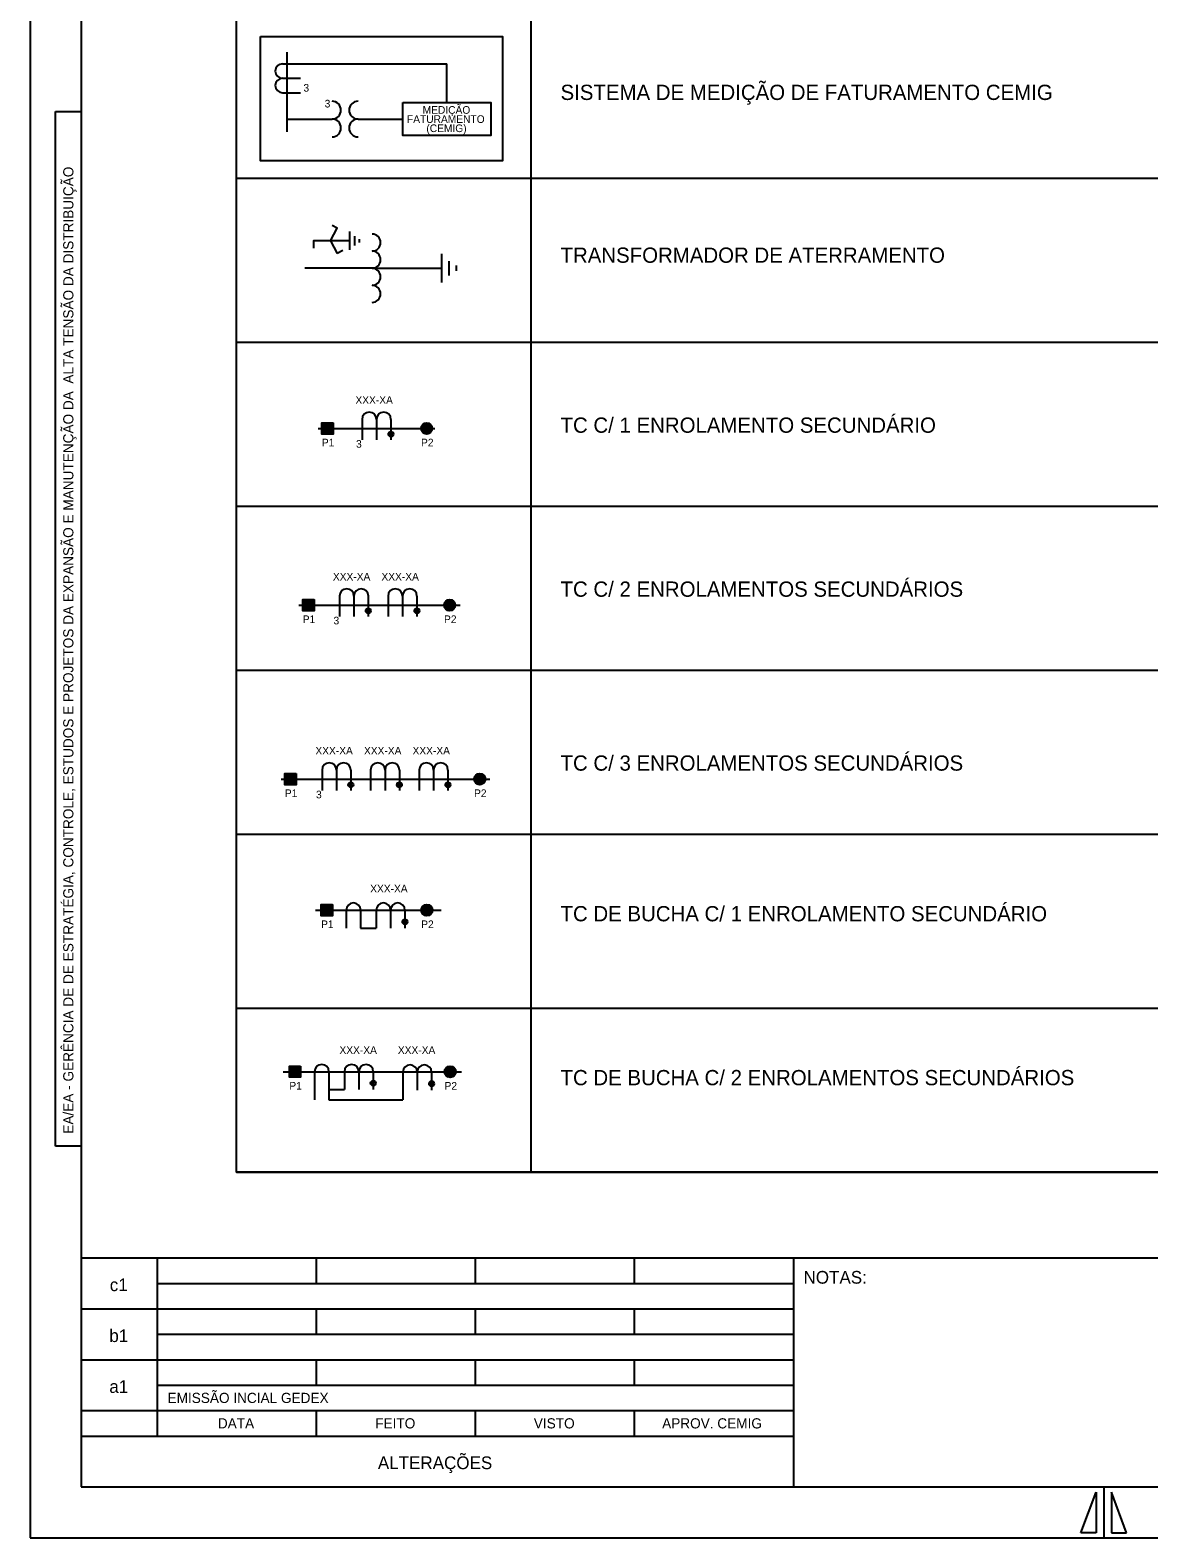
# Model space of a CAD drawing. Extents: x 563 to 3226, y 358 to 960.
# Drawn here: x 562.6 to 782.4, y 358 to 654.3 of the extents above; entities that cross this region are included whole.
import ezdxf

# ---------------------------------------------------------------- set-up
doc = ezdxf.new("R2010")
doc.units = 0
for name, color, linetype in [('11', 7, 'Continuous'), ('COMENTÁRIOS_CEMIG_03-12-2019', 7, 'Continuous'), ('Default', 7, 'Continuous'), ('Level 2', 7, 'Continuous'), ('New Level (0)', 7, 'Continuous')]:
    doc.layers.add(name, color=color, linetype=linetype)

msp = doc.modelspace()

# ---------------------------------------------------------------- linework, layer by layer
for p, q in [((627.23, 613.23), (627.23, 612.54)), ((646.28, 608.02), (646.28, 606.95))]:
    msp.add_line(p, q)
at = {"layer": '11'}
for p, q in [((621.62, 612.88), (622.94, 610.38)), ((624.02, 610.95), (622.94, 610.38)), ((629.78, 607.49), (616.59, 607.49)), ((630.42, 607.49), (629.78, 607.49))]:
    msp.add_line(p, q, dxfattribs=at)
for points in [[(621.62, 612.88), (622.91, 615.34), (621.94, 615.86)], [(625.43, 612.88), (618.29, 612.88), (618.29, 611.46)]]:
    msp.add_lwpolyline(points, dxfattribs=at)
at = {"layer": 'COMENTÁRIOS_CEMIG_03-12-2019'}
for p, q in [((619.91, 576.99), (622.01, 574.89)), ((619.91, 576.81), (621.83, 574.89)), ((619.91, 576.63), (621.65, 574.89)), ((619.91, 576.45), (621.48, 574.89)), ((619.91, 576.28), (621.3, 574.89)), ((619.91, 576.1), (621.12, 574.89)), ((619.91, 575.92), (620.95, 574.89)), ((619.91, 575.75), (620.77, 574.89)), ((619.91, 575.57), (620.59, 574.89)), ((619.91, 575.39), (620.42, 574.89)), ((619.91, 575.22), (620.24, 574.89)), ((619.91, 575.04), (620.06, 574.89)), ((619.97, 577.1), (622.13, 574.95)), ((620.15, 577.1), (622.13, 575.13)), ((620.33, 577.1), (622.13, 575.3)), ((620.5, 577.1), (622.13, 575.48)), ((620.68, 577.1), (622.13, 575.66)), ((620.86, 577.1), (622.13, 575.83)), ((621.03, 577.1), (622.13, 576.01)), ((621.21, 577.1), (622.13, 576.19)), ((621.39, 577.1), (622.13, 576.36)), ((621.56, 577.1), (622.13, 576.54)), ((621.74, 577.1), (622.13, 576.72)), ((621.92, 577.1), (622.13, 576.9)), ((622.09, 577.1), (622.13, 577.07)), ((616.21, 542.38), (618.37, 540.22)), ((616.39, 542.38), (618.37, 540.4)), ((616.57, 542.38), (618.37, 540.58)), ((616.74, 542.38), (618.37, 540.75)), ((616.92, 542.38), (618.37, 540.93)), ((617.1, 542.38), (618.37, 541.11)), ((617.27, 542.38), (618.37, 541.28)), ((617.45, 542.38), (618.37, 541.46)), ((617.63, 542.38), (618.37, 541.64)), ((617.8, 542.38), (618.37, 541.81)), ((617.98, 542.38), (618.37, 541.99)), ((618.16, 542.38), (618.37, 542.17)), ((618.33, 542.38), (618.37, 542.34)), ((616.16, 542.26), (618.25, 540.17)), ((616.16, 542.08), (618.07, 540.17)), ((616.16, 541.9), (617.89, 540.17)), ((616.16, 541.73), (617.72, 540.17)), ((616.16, 541.55), (617.54, 540.17)), ((616.16, 541.37), (617.36, 540.17)), ((616.16, 541.2), (617.19, 540.17)), ((616.16, 541.02), (617.01, 540.17)), ((616.16, 540.84), (616.83, 540.17)), ((616.16, 540.67), (616.66, 540.17)), ((616.16, 540.49), (616.48, 540.17)), ((616.16, 540.31), (616.3, 540.17)), ((612.64, 508.07), (614.73, 505.98)), ((612.64, 507.89), (614.55, 505.98)), ((612.64, 507.72), (614.38, 505.98)), ((612.64, 507.54), (614.2, 505.98)), ((612.64, 507.36), (614.02, 505.98)), ((612.64, 507.19), (613.85, 505.98)), ((612.64, 507.01), (613.67, 505.98)), ((612.64, 506.83), (613.49, 505.98)), ((612.7, 508.19), (614.85, 506.04)), ((612.87, 508.19), (614.85, 506.21)), ((613.05, 508.19), (614.85, 506.39)), ((613.23, 508.19), (614.85, 506.57)), ((613.4, 508.19), (614.85, 506.74)), ((613.58, 508.19), (614.85, 506.92)), ((613.76, 508.19), (614.85, 507.1)), ((613.93, 508.19), (614.85, 507.27)), ((614.11, 508.19), (614.85, 507.45)), ((614.29, 508.19), (614.85, 507.63)), ((614.46, 508.19), (614.85, 507.8)), ((614.64, 508.19), (614.85, 507.98)), ((614.82, 508.19), (614.85, 508.16)), ((612.64, 506.66), (613.32, 505.98)), ((612.64, 506.48), (613.14, 505.98)), ((612.64, 506.3), (612.96, 505.98)), ((612.64, 506.13), (612.79, 505.98)), ((619.76, 482.31), (621.85, 480.22)), ((619.76, 482.13), (621.67, 480.22)), ((619.76, 481.96), (621.5, 480.22)), ((619.76, 481.78), (621.32, 480.22)), ((619.76, 481.6), (621.14, 480.22)), ((619.76, 481.43), (620.97, 480.22)), ((619.76, 481.25), (620.79, 480.22)), ((619.76, 481.07), (620.61, 480.22)), ((619.76, 480.9), (620.44, 480.22)), ((619.76, 480.72), (620.26, 480.22)), ((619.76, 480.54), (620.08, 480.22)), ((619.76, 480.37), (619.91, 480.22)), ((619.82, 482.43), (621.97, 480.28)), ((619.99, 482.43), (621.97, 480.45)), ((620.17, 482.43), (621.97, 480.63)), ((620.35, 482.43), (621.97, 480.81)), ((620.52, 482.43), (621.97, 480.98)), ((620.7, 482.43), (621.97, 481.16)), ((620.88, 482.43), (621.97, 481.34)), ((621.05, 482.43), (621.97, 481.51)), ((621.23, 482.43), (621.97, 481.69)), ((621.41, 482.43), (621.97, 481.87)), ((621.58, 482.43), (621.97, 482.04)), ((621.76, 482.43), (621.97, 482.22)), ((621.94, 482.43), (621.97, 482.4)), ((613.52, 450.57), (615.61, 448.48)), ((613.58, 450.69), (615.73, 448.54)), ((613.75, 450.69), (615.73, 448.71)), ((613.93, 450.69), (615.73, 448.89)), ((614.11, 450.69), (615.73, 449.07)), ((614.28, 450.69), (615.73, 449.24)), ((614.46, 450.69), (615.73, 449.42)), ((614.64, 450.69), (615.73, 449.6)), ((614.81, 450.69), (615.73, 449.77)), ((614.99, 450.69), (615.73, 449.95)), ((615.17, 450.69), (615.73, 450.13)), ((615.34, 450.69), (615.73, 450.3)), ((615.52, 450.69), (615.73, 450.48)), ((615.7, 450.69), (615.73, 450.66)), ((613.52, 450.39), (615.43, 448.48)), ((613.52, 450.22), (615.26, 448.48)), ((613.52, 450.04), (615.08, 448.48)), ((613.52, 449.86), (614.9, 448.48)), ((613.52, 449.69), (614.73, 448.48)), ((613.52, 449.51), (614.55, 448.48)), ((613.52, 449.33), (614.37, 448.48)), ((613.52, 449.16), (614.2, 448.48)), ((613.52, 448.98), (614.02, 448.48)), ((613.52, 448.8), (613.84, 448.48)), ((613.52, 448.63), (613.67, 448.48))]:
    msp.add_line(p, q, dxfattribs=at)
for points in [[(622.13, 577.1), (622.13, 574.89), (619.91, 574.89), (619.91, 577.1)], [(618.37, 542.38), (618.37, 540.17), (616.16, 540.17), (616.16, 542.38)], [(614.85, 508.19), (614.85, 505.98), (612.64, 505.98), (612.64, 508.19)], [(621.97, 482.43), (621.97, 480.22), (619.76, 480.22), (619.76, 482.43)], [(615.73, 450.69), (615.73, 448.48), (613.52, 448.48), (613.52, 450.69)]]:
    msp.add_lwpolyline(points, close=True, dxfattribs=at)
at = {"layer": 'Default'}
for p, q in [((613.08, 634.27), (613.08, 649.98)), ((612.17, 647.65), (615.7, 647.65)), ((615.7, 647.65), (644.48, 647.65)), ((612.17, 644.82), (615.7, 644.82)), ((612.17, 641.99), (615.7, 641.99)), ((613.08, 636.81), (621.92, 636.81)), ((627.02, 636.81), (635.81, 636.81)), ((627.81, 577.78), (627.81, 573.77)), ((630.65, 577.78), (630.65, 573.77)), ((633.48, 577.78), (633.48, 573.77)), ((639.41, 576.08), (640.59, 574.9)), ((639.41, 575.88), (640.39, 574.9)), ((639.43, 576.25), (640.76, 574.92)), ((639.47, 575.62), (640.13, 574.96)), ((639.48, 576.4), (640.91, 574.97)), ((639.54, 576.53), (641.04, 575.03)), ((639.61, 576.65), (641.16, 575.1)), ((639.7, 576.76), (641.27, 575.19)), ((639.8, 576.85), (641.36, 575.29)), ((639.92, 576.93), (641.44, 575.41)), ((640.04, 577), (641.51, 575.53)), ((640.18, 577.06), (641.57, 575.67)), ((640.34, 577.09), (641.6, 575.83)), ((640.53, 577.1), (641.61, 576.02)), ((640.75, 577.08), (641.59, 576.24)), ((641.07, 576.95), (641.46, 576.56)), ((623.38, 543.05), (623.38, 539.04)), ((626.21, 543.05), (626.21, 539.04)), ((629.04, 543.05), (629.04, 539.04)), ((632.93, 543.05), (632.93, 539.04)), ((635.76, 543.05), (635.76, 539.04)), ((638.59, 543.05), (638.59, 539.04)), ((644.7, 542.33), (646.08, 540.95)), ((644.86, 542.36), (646.12, 541.11)), ((645.04, 542.38), (646.13, 541.29)), ((645.27, 542.35), (646.1, 541.51)), ((643.92, 541.35), (645.1, 540.17)), ((643.93, 541.15), (644.9, 540.17)), ((643.95, 541.52), (645.27, 540.19)), ((643.99, 541.67), (645.42, 540.24)), ((643.99, 540.89), (644.65, 540.23)), ((644.06, 541.8), (645.56, 540.3)), ((644.13, 541.92), (645.68, 540.38)), ((644.22, 542.03), (645.78, 540.47)), ((644.32, 542.12), (645.88, 540.57)), ((644.43, 542.2), (645.96, 540.68)), ((644.56, 542.27), (646.03, 540.81)), ((645.59, 542.22), (645.98, 541.83)), ((619.95, 508.87), (619.95, 504.85)), ((622.78, 508.87), (622.78, 504.85)), ((625.61, 508.87), (625.61, 504.85)), ((629.49, 508.87), (629.49, 504.85)), ((632.32, 508.87), (632.32, 504.85)), ((635.15, 508.87), (635.15, 504.85)), ((639.03, 508.87), (639.03, 504.85)), ((641.86, 508.87), (641.86, 504.85)), ((644.69, 508.87), (644.69, 504.85)), ((649.83, 507.16), (651.01, 505.98)), ((649.83, 506.96), (650.81, 505.98)), ((649.85, 507.33), (651.18, 506.01)), ((649.9, 507.48), (651.33, 506.05)), ((649.96, 507.61), (651.46, 506.11)), ((650.04, 507.73), (651.58, 506.19)), ((650.13, 507.84), (651.69, 506.28)), ((650.23, 507.93), (651.78, 506.38)), ((650.34, 508.02), (651.87, 506.49)), ((650.47, 508.09), (651.93, 506.62)), ((650.61, 508.14), (651.99, 506.76)), ((650.77, 508.18), (652.02, 506.92)), ((650.95, 508.19), (652.04, 507.1)), ((651.17, 508.16), (652.01, 507.32)), ((651.5, 508.03), (651.88, 507.65)), ((649.89, 506.71), (650.55, 506.04)), ((618.64, 481.32), (643.37, 481.34)), ((624.7, 481.32), (624.7, 477.81)), ((627.53, 481.32), (627.53, 477.79)), ((630.58, 481.32), (630.58, 477.79)), ((633.41, 481.32), (633.41, 477.79)), ((636.24, 481.32), (636.24, 477.79)), ((639.45, 481.4), (640.63, 480.22)), ((639.45, 481.2), (640.43, 480.22)), ((639.47, 481.57), (640.8, 480.25)), ((639.51, 480.95), (640.17, 480.28)), ((639.52, 481.72), (640.95, 480.29)), ((639.58, 481.85), (641.08, 480.35)), ((639.66, 481.97), (641.2, 480.43)), ((639.75, 482.08), (641.31, 480.52)), ((639.85, 482.18), (641.4, 480.62)), ((639.96, 482.26), (641.49, 480.73)), ((640.09, 482.33), (641.55, 480.86)), ((640.23, 482.38), (641.61, 481)), ((640.39, 482.42), (641.65, 481.16)), ((640.57, 482.43), (641.66, 481.34)), ((640.79, 482.4), (641.63, 481.56)), ((641.12, 482.27), (641.5, 481.89)), ((627.53, 477.79), (630.58, 477.79)), ((644.43, 450.42), (645.98, 448.86)), ((644.54, 450.5), (646.07, 448.97)), ((644.67, 450.57), (646.14, 449.1)), ((644.81, 450.62), (646.19, 449.24)), ((644.97, 450.66), (646.23, 449.4)), ((645.15, 450.67), (646.24, 449.58)), ((645.37, 450.65), (646.21, 449.81)), ((645.7, 450.52), (646.08, 450.13)), ((612.33, 449.58), (647.35, 449.58)), ((618.46, 449.58), (618.46, 444.05)), ((618.46, 449.58), (618.46, 444.05)), ((621.29, 449.58), (621.29, 446.05)), ((621.29, 449.58), (621.29, 444.05)), ((624.34, 449.58), (624.34, 446.05)), ((624.34, 449.58), (624.34, 446.05)), ((627.17, 449.58), (627.17, 446.05)), ((627.17, 449.58), (627.17, 446.05)), ((630, 449.58), (630, 446.05)), ((630, 449.58), (630, 446.05)), ((635.82, 449.49), (635.82, 444.05)), ((638.65, 449.49), (638.65, 445.96)), ((641.48, 449.49), (641.48, 445.96)), ((644.03, 449.64), (645.21, 448.46)), ((644.03, 449.44), (645.01, 448.47)), ((644.05, 449.81), (645.38, 448.49)), ((644.09, 449.19), (644.75, 448.53)), ((644.1, 449.96), (645.53, 448.53)), ((644.16, 450.1), (645.66, 448.6)), ((644.24, 450.22), (645.78, 448.67)), ((644.33, 450.32), (645.89, 448.76)), ((621.29, 446.05), (624.34, 446.05)), ((621.29, 444.05), (635.82, 444.05))]:
    msp.add_line(p, q, dxfattribs=at)
for centre, radius in [((633.48, 574.89), 0.501), ((633.48, 574.89), 0.282), ((640.51, 576), 1.11), ((645.03, 541.27), 1.11), ((629.04, 540.17), 0.501), ((629.04, 540.17), 0.282), ((638.59, 540.17), 0.501), ((638.59, 540.17), 0.282), ((650.93, 507.08), 1.11), ((625.61, 505.98), 0.501), ((625.61, 505.98), 0.282), ((635.15, 505.98), 0.501), ((635.15, 505.98), 0.282), ((644.69, 505.98), 0.501), ((644.69, 505.98), 0.282), ((640.55, 481.32), 1.11), ((636.24, 479.05), 0.501), ((636.24, 479.05), 0.282), ((645.13, 449.57), 1.11), ((630, 447.32), 0.501), ((630, 447.32), 0.282), ((641.48, 447.22), 0.501), ((641.48, 447.22), 0.282)]:
    msp.add_circle(centre, radius, dxfattribs=at)
for centre, radius, start, end in [((612.17, 646.24), 1.42, 90, 270), ((612.17, 643.41), 1.42, 90, 270), ((621.92, 638.56), 1.75, 270, 90), ((627.02, 638.56), 1.75, 90, 270), ((621.92, 635.06), 1.75, 270, 90), ((627.02, 635.06), 1.75, 90, 270), ((629.78, 612.53), 1.68, 270, 90), ((629.78, 609.17), 1.68, 270, 90), ((629.78, 605.81), 1.68, 270, 90), ((629.78, 602.45), 1.68, 270, 90), ((629.23, 577.78), 1.42, 0, 180), ((632.06, 577.78), 1.42, 0, 180), ((624.8, 543.05), 1.42, 0, 180), ((627.63, 543.05), 1.42, 0, 180), ((634.34, 543.05), 1.42, 0, 180), ((637.17, 543.05), 1.42, 0, 180), ((621.36, 508.87), 1.42, 0, 180), ((624.19, 508.87), 1.42, 0, 180), ((630.91, 508.87), 1.42, 0, 180), ((633.74, 508.87), 1.42, 0, 180), ((640.45, 508.87), 1.42, 0, 180), ((643.28, 508.87), 1.42, 0, 180), ((626.12, 481.32), 1.42, 0, 180), ((632, 481.32), 1.42, 0, 180), ((634.83, 481.32), 1.42, 0, 180), ((619.88, 449.58), 1.42, 0, 180), ((619.88, 449.58), 1.42, 0, 180), ((625.76, 449.58), 1.42, 0, 180), ((625.76, 449.58), 1.42, 0, 180), ((628.59, 449.58), 1.42, 0, 180), ((628.59, 449.58), 1.42, 0, 180), ((637.24, 449.49), 1.42, 0, 180), ((640.07, 449.49), 1.42, 0, 180)]:
    msp.add_arc(centre, radius, start, end, dxfattribs=at)
at = {"layer": 'Level 2'}
for p, q in [((625.43, 611.09), (625.43, 614.68)), ((626.33, 613.78), (626.33, 611.99)), ((629.78, 607.49), (643.48, 607.49)), ((643.48, 604.69), (643.48, 610.29)), ((644.88, 608.89), (644.88, 606.09))]:
    msp.add_line(p, q, dxfattribs=at)
at = {"layer": 'New Level (0)'}
for p, q in [((562.58, 951.96), (562.58, 357.96)), ((562.58, 951.96), (562.58, 357.96)), ((572.58, 941.96), (572.58, 367.96)), ((572.58, 941.96), (572.58, 367.96)), ((660.98, 925.28), (660.98, 429.83)), ((644.48, 640.04), (644.48, 647.65)), ((567.58, 638.29), (572.58, 638.29)), ((567.58, 434.97), (567.58, 638.29)), ((603.14, 625.16), (953.22, 625.16)), ((603.14, 592.93), (1303.31, 592.93)), ((619.17, 576), (642.12, 576)), ((603.14, 560.7), (1303.31, 560.7)), ((615.41, 541.27), (647.11, 541.27)), ((603.14, 528.47), (1303.31, 528.47)), ((603.14, 528.47), (1303.31, 528.47)), ((611.89, 507.08), (652.94, 507.08)), ((603.14, 496.25), (1303.31, 496.25)), ((603.14, 462.06), (1303.31, 462.06)), ((572.58, 434.97), (567.58, 434.97)), ((603.14, 429.83), (1303.31, 429.83)), ((572.58, 412.96), (1393.58, 412.96)), ((587.58, 377.96), (587.58, 412.96)), ((618.83, 407.96), (618.83, 412.96)), ((650.08, 407.96), (650.08, 412.96)), ((681.33, 407.96), (681.33, 412.96)), ((712.58, 412.96), (712.58, 367.96)), ((587.58, 407.96), (712.58, 407.96)), ((572.58, 402.96), (712.58, 402.96)), ((618.83, 397.96), (618.83, 402.96)), ((650.08, 397.96), (650.08, 402.96)), ((681.33, 397.96), (681.33, 402.96)), ((587.58, 397.96), (712.58, 397.96)), ((572.58, 392.96), (712.58, 392.96)), ((618.83, 387.96), (618.83, 392.96)), ((650.08, 387.96), (650.08, 392.96)), ((681.33, 387.96), (681.33, 392.96)), ((587.58, 387.96), (712.58, 387.96)), ((572.58, 382.96), (712.58, 382.96)), ((618.83, 377.96), (618.83, 382.96)), ((650.08, 377.96), (650.08, 382.96)), ((681.33, 377.96), (681.33, 382.96)), ((572.58, 377.96), (712.58, 377.96)), ((572.58, 367.96), (1393.58, 367.96)), ((572.58, 367.96), (1393.58, 367.96)), ((773.58, 367.96), (773.58, 357.96)), ((769.08, 358.96), (772.08, 366.96)), ((772.08, 366.96), (772.08, 358.96)), ((775.08, 366.96), (775.08, 358.96)), ((778.08, 358.96), (775.08, 366.96)), ((772.08, 358.96), (769.08, 358.96)), ((775.08, 358.96), (778.08, 358.96)), ((562.58, 357.96), (1403.58, 357.96)), ((562.58, 357.96), (1403.58, 357.96))]:
    msp.add_line(p, q, dxfattribs=at)
for points in [[(603.14, 915.21), (807.1, 915.21), (807.1, 429.83), (603.14, 429.83)], [(607.84, 653.05), (655.43, 653.05), (655.43, 628.62), (607.84, 628.62)], [(635.81, 640.04), (653.15, 640.04), (653.15, 633.57), (635.81, 633.57)]]:
    msp.add_lwpolyline(points, close=True, dxfattribs=at)

# ---------------------------------------------------------------- texts
at = {"layer": 'Default'}
for s, height, p in [('3', 1.5, (616.29, 642.2)), ('SISTEMA DE MEDIÇÃO DE FATURAMENTO CEMIG', 3, (666.82, 640.56)), ('3', 1.5, (620.46, 639.09)), ('FATURAMENTO', 1.5, (636.64, 636.05)), ('MEDIÇÃO', 1.5, (639.72, 637.85)), ('(CEMIG)', 1.5, (640.45, 634.25)), ('TRANSFORMADOR DE ATERRAMENTO', 3, (666.82, 608.56)), ('TC C/ 1 ENROLAMENTO SECUNDÁRIO', 3, (666.82, 575.15)), ('P1', 1.5, (619.91, 572.48)), ('3', 1.5, (626.63, 572.22)), ('P2', 1.5, (639.4, 572.48)), ('TC C/ 2 ENROLAMENTOS SECUNDÁRIOS', 3, (666.82, 542.92)), ('P1', 1.5, (616.15, 537.75)), ('3', 1.5, (622.2, 537.49)), ('P2', 1.5, (643.92, 537.75)), ('TC C/ 3 ENROLAMENTOS SECUNDÁRIOS', 3, (666.82, 508.74)), ('P1', 1.5, (612.64, 503.56)), ('3', 1.5, (618.76, 503.3)), ('P2', 1.5, (649.82, 503.56)), ('XXX-XA', 1.5, (629.41, 484.81)), ('TC DE BUCHA C/ 1 ENROLAMENTO SECUNDÁRIO', 3, (666.82, 479.13)), ('P1', 1.5, (619.76, 477.8)), ('P2', 1.5, (639.44, 477.8)), ('XXX-XA', 1.5, (623.37, 453.07)), ('XXX-XA', 1.5, (634.85, 453.07)), ('TC DE BUCHA C/ 2 ENROLAMENTOS SECUNDÁRIOS', 3, (666.82, 446.91)), ('P1', 1.5, (613.52, 446.06)), ('P2', 1.5, (644.03, 446.04))]:
    msp.add_text(s, height=height, dxfattribs=at).set_placement(p)
for p in [(626.51, 580.84), (622.08, 546.11), (631.62, 546.11), (618.64, 511.92), (628.19, 511.92), (637.73, 511.92)]:
    msp.add_text('XXX-XA', height=1.5, rotation=360, dxfattribs=at).set_placement(p)
at = {"layer": 'New Level (0)'}
msp.add_text('EA/EA - GERÊNCIA DE DE ESTRATÉGIA, CONTROLE, ESTUDOS E PROJETOS DA EXPANSÃO E MANUTENÇÃO DA  ALTA TENSÃO DA DISTRIBUIÇÃO', height=2, rotation=90, dxfattribs=at).set_placement((571.08, 437.39))
for s, height, p in [('c1', 2.5, (578.23, 406.44)), ('NOTAS:', 2.5, (714.58, 407.91)), ('b1', 2.5, (578.14, 396.44)), ('a1', 2.5, (578.14, 386.44)), ('EMISSÃO INCIAL GEDEX', 2, (589.58, 384.46)), ('DATA', 2, (599.47, 379.46)), ('FEITO', 2, (630.4, 379.46)), ('VISTO', 2, (661.57, 379.46)), ('APROV. CEMIG', 2, (686.79, 379.46)), ('ALTERAÇÕES', 2.5, (630.92, 371.46))]:
    msp.add_text(s, height=height, dxfattribs=at).set_placement(p)

doc.saveas('drawing.dxf')
